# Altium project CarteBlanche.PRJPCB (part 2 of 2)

## Sheet FPGAPOWER.SchDoc: FPGA POWER CONFIG.
size A4; PageSetup: Record=PageOptions|CenterHorizontal=True|CenterVertical=True|PrintScale=0.70|XCorrection=1.00|YCorrection=1.00|PrintKind=0|BorderSize=5000000|LeftOffset=0|BottomOffset=0|Orientation=2|PaperLength=1000|PaperWidth=1000|Scale=100|PaperSource=7|PrintQuality=1200|MediaType=1|DitherType=10|PaperKind=A4 (210 x 297 mm)|PrintScaleMode=1; CheckedBy: SRKH; Author: SRKH; Engineer: SRKH; DocumentNumber: 3; Revision: CB500E; SheetNumber: 3; SheetTotal: 18; DrawnBy: SRKH; Address1: WWW.APPLELOGIC.ORG
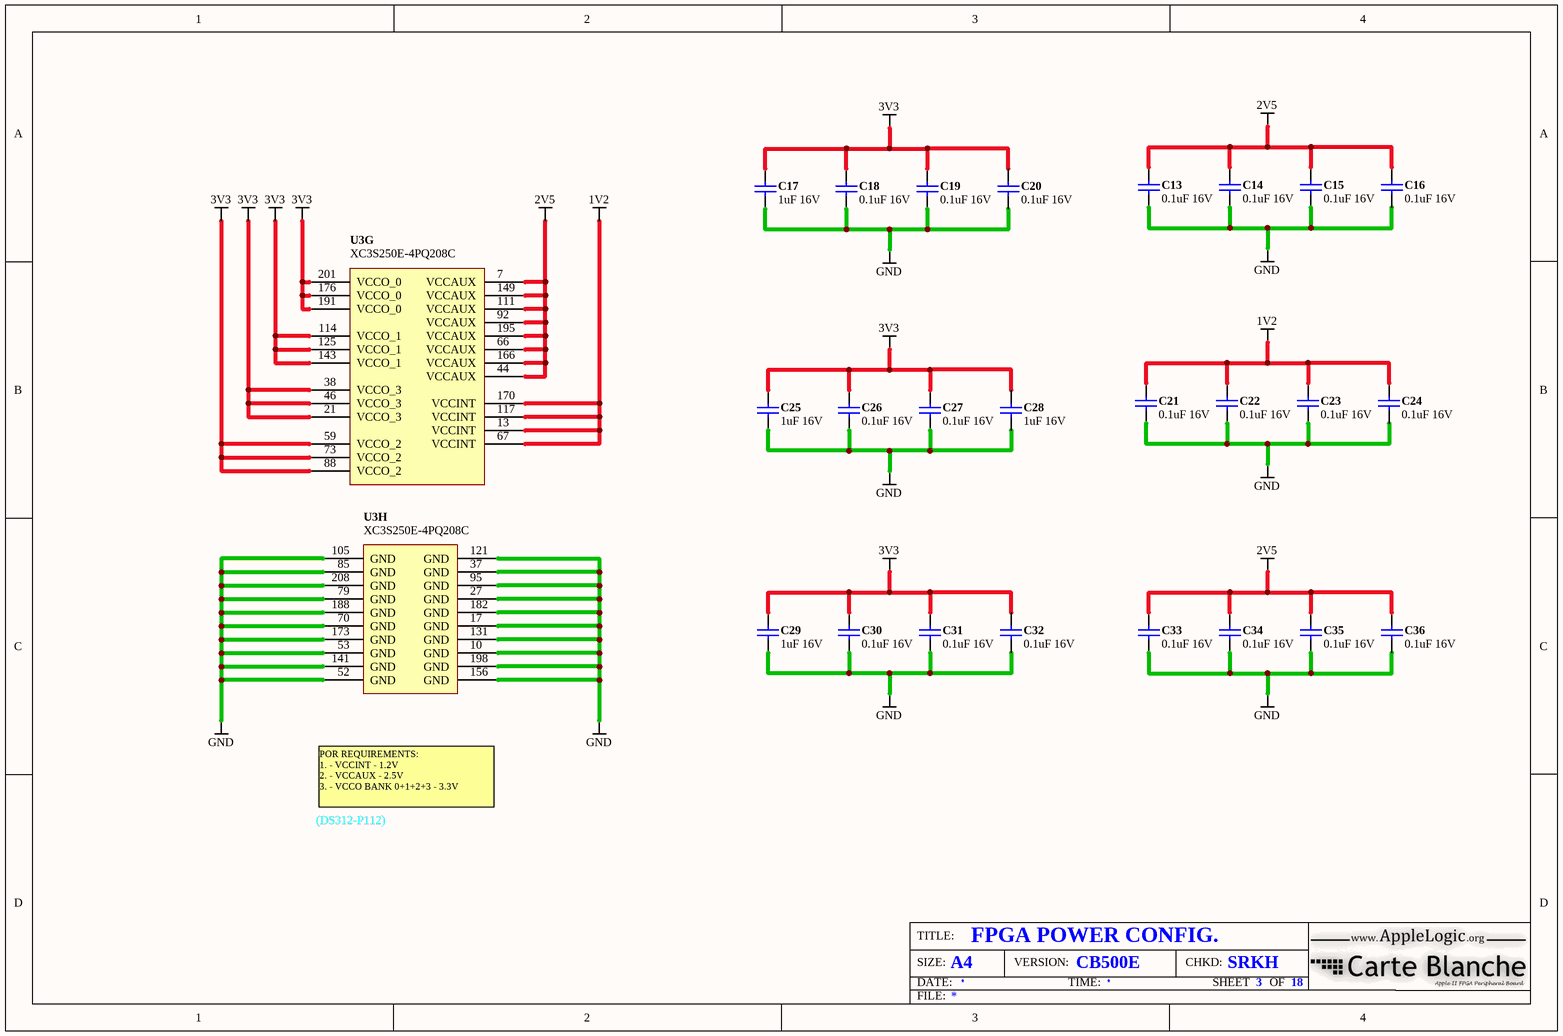
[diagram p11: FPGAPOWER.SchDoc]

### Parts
(Parts that share a designator on the sheet are numbered #1, #2 ... from top to bottom, then left to right.)
C13  0.1uF 16V  [CAPC1005-STAR]
C14  0.1uF 16V  [CAPC1005-STAR]
C15  0.1uF 16V  [CAPC1005-STAR]
C16  0.1uF 16V  [CAPC1005-STAR]
C17  1uF 16V  [CAPC1005-STAR]
C18  0.1uF 16V  [CAPC1005-STAR]
C19  0.1uF 16V  [CAPC1005-STAR]
C20  0.1uF 16V  [CAPC1005-STAR]
C21  0.1uF 16V  [CAPC1005-STAR]
C22  0.1uF 16V  [CAPC1005-STAR]
C23  0.1uF 16V  [CAPC1005-STAR]
C24  0.1uF 16V  [CAPC1005-STAR]
C25  1uF 16V  [CAPC1005-STAR]
C26  0.1uF 16V  [CAPC1005-STAR]
C27  0.1uF 16V  [CAPC1005-STAR]
C28  1uF 16V  [CAPC1005-STAR]
C29  1uF 16V  [CAPC1005-STAR]
C30  0.1uF 16V  [CAPC1005-STAR]
C31  0.1uF 16V  [CAPC1005-STAR]
C32  0.1uF 16V  [CAPC1005-STAR]
C33  0.1uF 16V  [CAPC1005-STAR]
C34  0.1uF 16V  [CAPC1005-STAR]
C35  0.1uF 16V  [CAPC1005-STAR]
C36  0.1uF 16V  [CAPC1005-STAR]
U3#1  XC3S250E-4PQ208C  [PQ208_N]  (part H of 8)
U3#2  XC3S250E-4PQ208C  [PQ208_N]  (part G of 8)

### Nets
1V2: C21.2 C22.2 C23.2 C24.1 U3#2.13(VCCINT) U3#2.67(VCCINT) U3#2.117(VCCINT) U3#2.170(VCCINT)
2V5: C13.2 C14.2 C15.2 C16.1 C33.2 C34.2 C35.2 C36.1 U3#2.7(VCCAUX) U3#2.44(VCCAUX) U3#2.66(VCCAUX) U3#2.92(VCCAUX) U3#2.111(VCCAUX) U3#2.149(VCCAUX) U3#2.166(VCCAUX) U3#2.195(VCCAUX)
3V3: C17.1 C18.1 C19.2 C20.2 C25.2 C26.2 C27.2 C28.2 C29.2 C30.2 C31.2 C32.2 U3#2.21(VCCO_3) U3#2.38(VCCO_3) U3#2.46(VCCO_3) U3#2.59(VCCO_2) U3#2.73(VCCO_2) U3#2.88(VCCO_2) U3#2.114(VCCO_1) U3#2.125(VCCO_1) U3#2.143(VCCO_1) U3#2.176(VCCO_0) U3#2.191(VCCO_0) U3#2.201(VCCO_0)
GND: C13.1 C14.1 C15.1 C16.2 C17.2 C18.2 C19.1 C20.1 C21.1 C22.1 C23.1 C24.2 C25.1 C26.1 C27.1 C28.1 C29.1 C30.1 C31.1 C32.1 C33.1 C34.1 C35.1 C36.2 U3#1.10(GND) U3#1.17(GND) U3#1.27(GND) U3#1.37(GND) U3#1.52(GND) U3#1.53(GND) U3#1.70(GND) U3#1.79(GND) U3#1.85(GND) U3#1.95(GND) U3#1.105(GND) U3#1.121(GND) U3#1.131(GND) U3#1.141(GND) U3#1.156(GND) U3#1.173(GND) U3#1.182(GND) U3#1.188(GND) U3#1.198(GND) U3#1.208(GND)

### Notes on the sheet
- (DS312-P112)
- POR REQUIREMENTS:
  1. - VCCINT - 1.2V
  2. - VCCAUX - 2.5V
  3. - VCCO BANK 0+1+2+3 - 3.3V

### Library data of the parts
C13-C36 = CAP-NP: Capacitor, Ceramic, 1uF 10% 16V 0402 (1005) X7R
U3#1 = XC3S500E-4PQ208C: IC SPARTAN-3E FPGA 500K 208-PQFP; EnablePinSwap: True
U3#2 = XC3S250E-4PQ208C: IC SPARTAN-3E FPGA 500K 208-PQFP; EnablePinSwap: True

## Sheet SRAM-128Kx8x2.SchDoc: 256K x8 SRAM MEMORY
size A4; PageSetup: Record=PageOptions|CenterHorizontal=True|CenterVertical=True|PrintScale=0.50|XCorrection=1.00|YCorrection=1.00|PrintKind=0|BorderSize=5000000|LeftOffset=0|BottomOffset=0|Orientation=2|PaperLength=1000|PaperWidth=1000|Scale=100|PaperSource=7|PrintQuality=600|MediaType=1|DitherType=10|PaperKind=12" x 18"|PrintScaleMode=1; CheckedBy: SRKH; Author: SRKH; Engineer: SRKH; DocumentNumber: 11; Revision: CB500E; SheetNumber: 11; SheetTotal: 18; DrawnBy: SRKH; Address1: WWW.APPLELOGIC.ORG
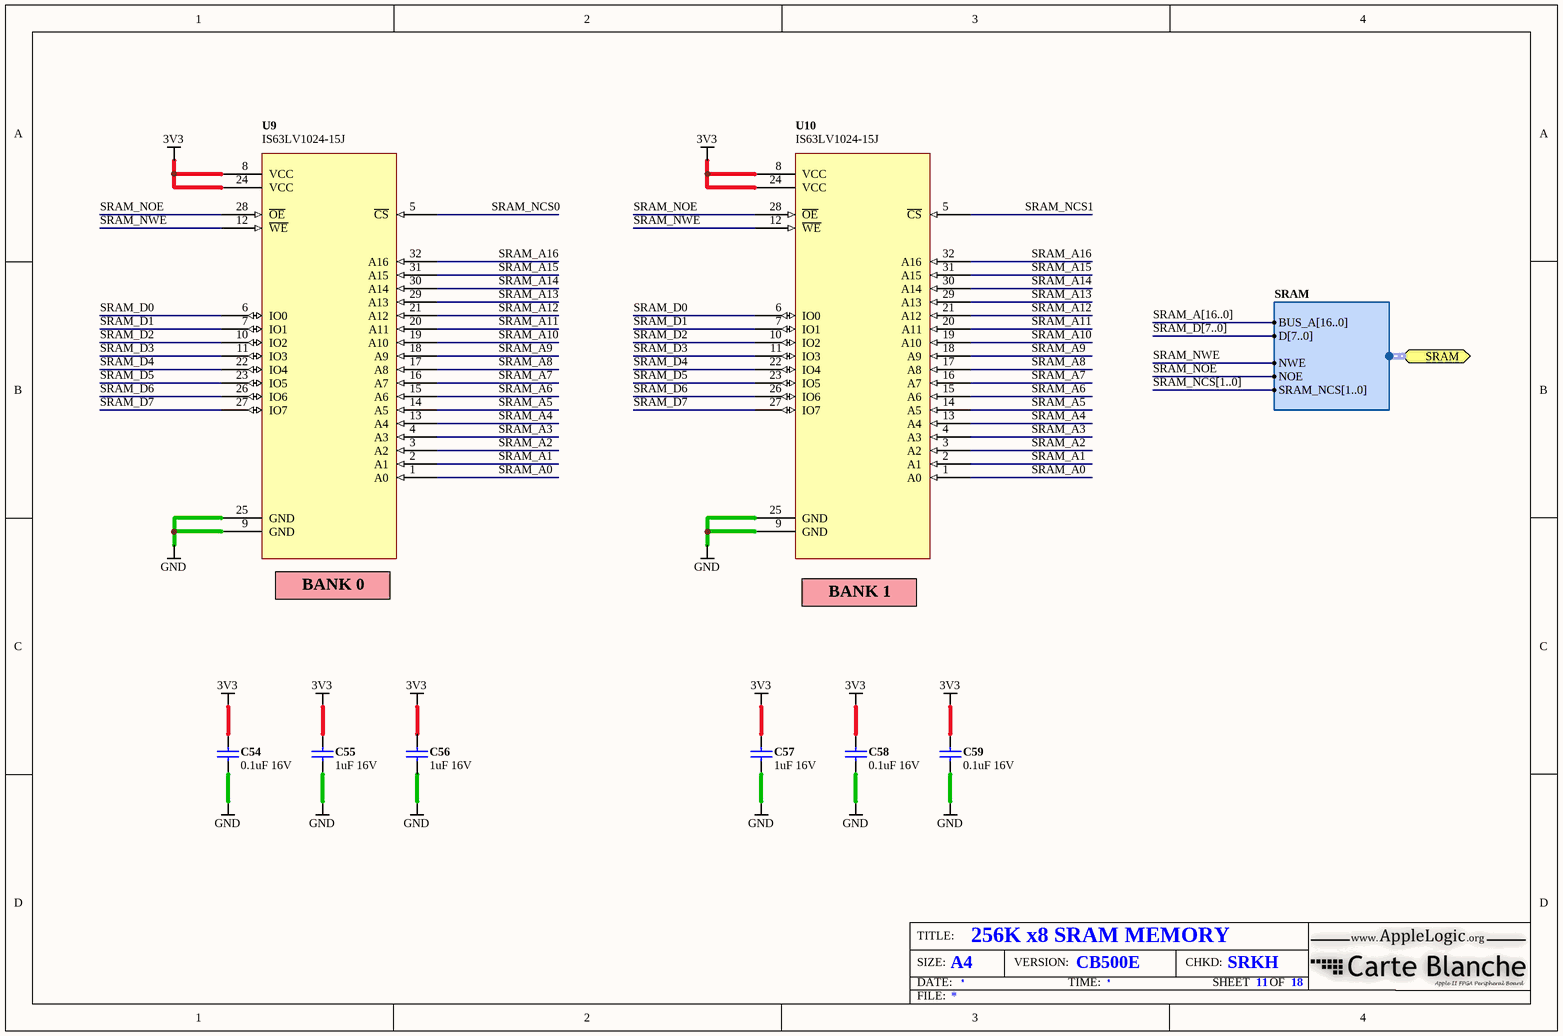
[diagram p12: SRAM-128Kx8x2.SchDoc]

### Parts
C54  0.1uF 16V  [CAPC1005-STAR]
C55  1uF 16V  [CAPC1005-STAR]
C56  1uF 16V  [CAPC1005-STAR]
C57  1uF 16V  [CAPC1005-STAR]
C58  0.1uF 16V  [CAPC1005-STAR]
C59  0.1uF 16V  [CAPC1005-STAR]
U9  IS63LV1024-15J  [SO-J32]
U10  IS63LV1024-15J  [SO-J32]

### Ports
SRAM (harness SRAM)

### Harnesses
SRAM: BUS_A[16..0], D[7..0], NWE, SRAM_NCS[1..0], NOE

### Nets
3V3: C54.1 C55.1 C56.1 C57.1 C58.1 C59.1 U9.8(VCC) U9.24(VCC) U10.8(VCC) U10.24(VCC)
GND: C54.2 C55.2 C56.2 C57.2 C58.2 C59.2 U9.9(GND) U9.25(GND) U10.9(GND) U10.25(GND)
SRAM_A0: U9.1(A0) U10.1(A0)
SRAM_A1: U9.2(A1) U10.2(A1)
SRAM_A2: U9.3(A2) U10.3(A2)
SRAM_A3: U9.4(A3) U10.4(A3)
SRAM_A4: U9.13(A4) U10.13(A4)
SRAM_A5: U9.14(A5) U10.14(A5)
SRAM_A6: U9.15(A6) U10.15(A6)
SRAM_A7: U9.16(A7) U10.16(A7)
SRAM_A8: U9.17(A8) U10.17(A8)
SRAM_A9: U9.18(A9) U10.18(A9)
SRAM_A10: U9.19(A10) U10.19(A10)
SRAM_A11: U9.20(A11) U10.20(A11)
SRAM_A12: U9.21(A12) U10.21(A12)
SRAM_A13: U9.29(A13) U10.29(A13)
SRAM_A14: U9.30(A14) U10.30(A14)
SRAM_A15: U9.31(A15) U10.31(A15)
SRAM_A16: U9.32(A16) U10.32(A16)
SRAM_D0: U9.6(IO0) U10.6(IO0)
SRAM_D1: U9.7(IO1) U10.7(IO1)
SRAM_D2: U9.10(IO2) U10.10(IO2)
SRAM_D3: U9.11(IO3) U10.11(IO3)
SRAM_D4: U9.22(IO4) U10.22(IO4)
SRAM_D5: U9.23(IO5) U10.23(IO5)
SRAM_D6: U9.26(IO6) U10.26(IO6)
SRAM_D7: U9.27(IO7) U10.27(IO7)
SRAM_NCS0: U9.5(~{CS})
SRAM_NCS1: U10.5(~{CS})
SRAM_NOE: U9.28(~{OE}) U10.28(~{OE}) ; port SRAM.NOE  [project net RAM.NOE]
SRAM_NWE: U9.12(~{WE}) U10.12(~{WE}) ; port SRAM.NWE  [project net RAM.NWE]

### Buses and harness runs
bus SRAM_A[16..0]
bus SRAM_D[7..0]
bus SRAM_NCS[1..0]

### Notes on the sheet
- (near U9) BANK 0
- (near U10) BANK 1

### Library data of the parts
C54-C59 = CAP-NP: as C13-C36 on sheet FPGAPOWER
U9 U10 = IDT71V124SA15Y: IC SRAM 128Kx8 15nS ASYNC 32-SOJ

## Sheet M25Pxx SPI_BOOT.SchDoc: SPI SYSTEM BOOT FLASH
size A4; PageSetup: Record=PageOptions|CenterHorizontal=True|CenterVertical=True|PrintScale=1.00|XCorrection=1.00|YCorrection=1.00|PrintKind=0|BorderSize=5000000|LeftOffset=0|BottomOffset=0|Orientation=2|PaperLength=1000|PaperWidth=1000|Scale=100|PaperSource=7|PrintQuality=600|MediaType=1|DitherType=10|PaperKind=12" x 18"|PrintScaleMode=1; CheckedBy: SRKH; Author: SRKH; Engineer: SRKH; DocumentNumber: 12; Revision: CB500E; SheetNumber: 12; SheetTotal: 18; DrawnBy: SRKH; Address1: WWW.APPLELOGIC.ORG
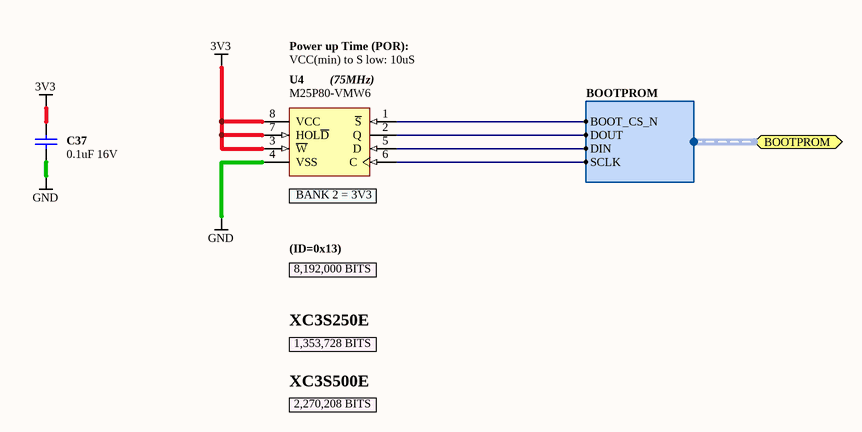
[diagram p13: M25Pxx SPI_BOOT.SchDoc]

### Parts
C37  0.1uF 16V  [CAPC1005-STAR]
U4  M25P80-VMW6  [SOIC8-200-BODY]

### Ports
BOOTPROM (harness BOOTPROM)

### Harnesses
BOOTPROM: DIN, DOUT, SCLK, BOOT_CS_N

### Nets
3V3: C37.1 U4.3(~{W}) U4.7(HOL~{D}) U4.8(VCC)
GND: C37.2 U4.4(VSS)
ROM.BOOT_CS_N: U4.1(~{S}) ; port BOOTPROM.BOOT_CS_N
ROM.DIN: U4.5(D) ; port BOOTPROM.DIN
ROM.DOUT: U4.2(Q) ; port BOOTPROM.DOUT
ROM.SCLK: U4.6(C) ; port BOOTPROM.SCLK

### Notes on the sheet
- Power up Time (POR):
- VCC(min) to S low: 10uS
- (near U4) (75MHz)
- (near U4) BANK 2 = 3V3
- (ID=0x13)
- 8,192,000 BITS
- XC3S250E
- 1,353,728 BITS
- XC3S500E
- 2,270,208 BITS

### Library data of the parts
C37 = CAP-NP: as C13-C36 on sheet FPGAPOWER
U4 = M25P80: IC SERIAL FLASH 8MBIT 3V 8-SOIC WIDE

## Sheet SVGA.SchDoc: SVGA 2BPP VIDEO PORT
size A4; CheckedBy: SRKH; Author: SRKH; DrawnBy: SRKH; Engineer: SRKH; Address1: WWW.APPLELOGIC.ORG; DocumentNumber: 13; Revision: CB500E; SheetNumber: 13; SheetTotal: 18
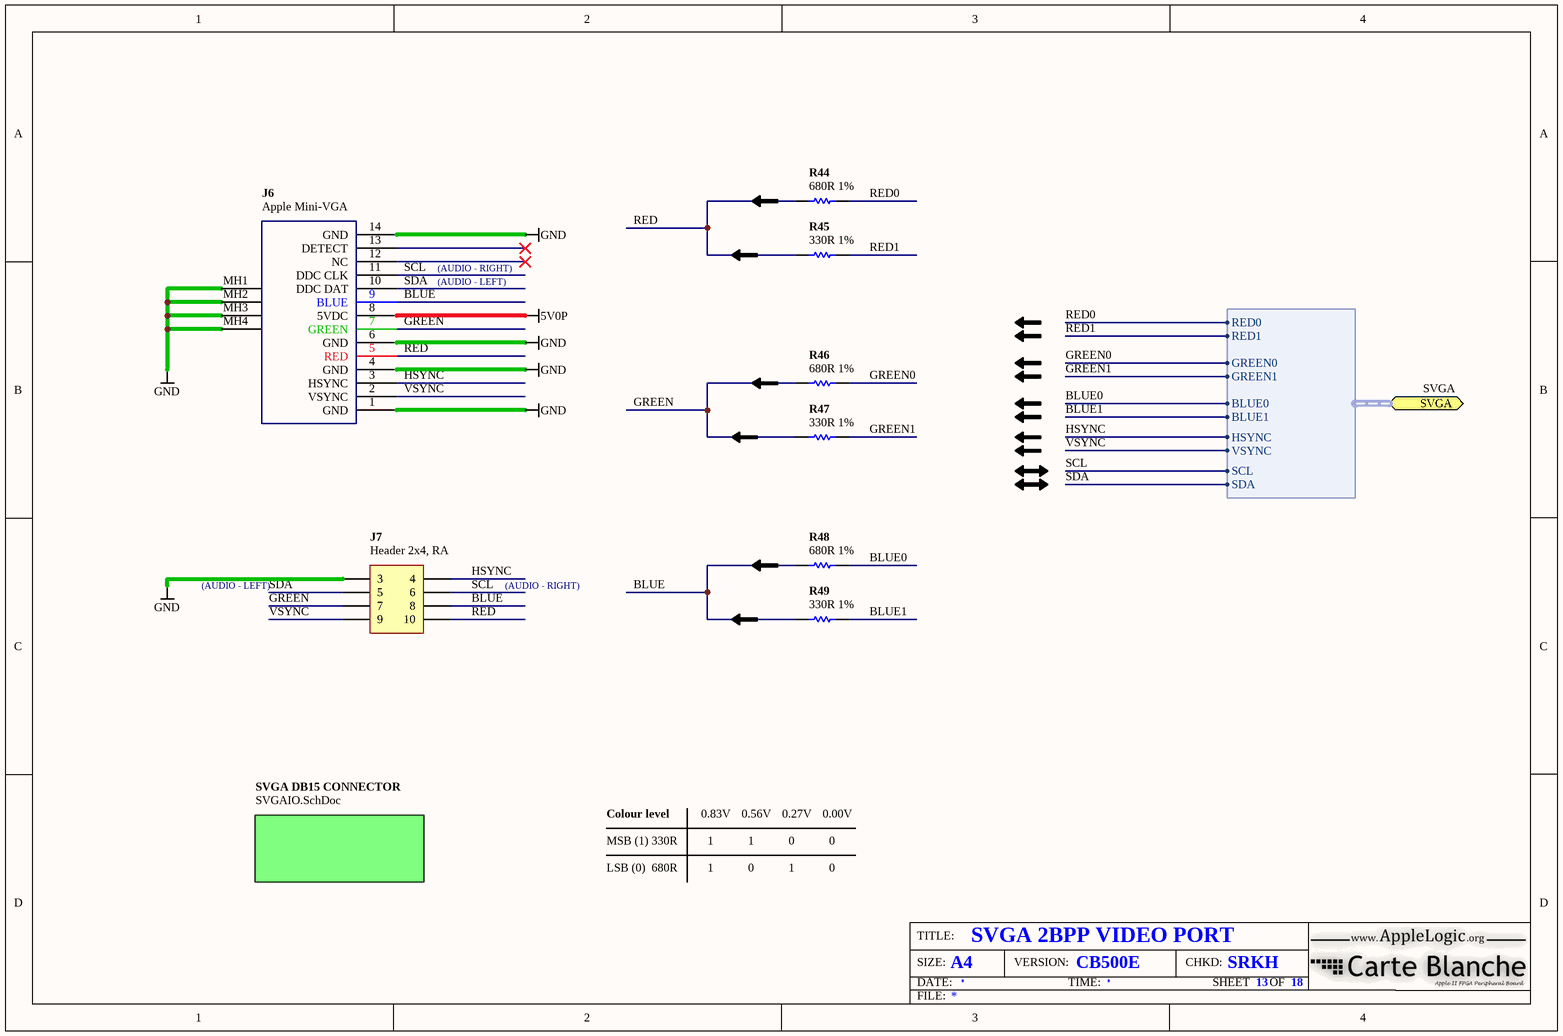
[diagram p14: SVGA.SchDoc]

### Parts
J6  Apple Mini-VGA  [CON_MINI_VGA]  (no BOM)
J7  Header 2x4, RA  [HDR2X4H]
R44  680R 1%  [RESC1005-STAR]
R45  330R 1%  [RESC1005-STAR]
R46  680R 1%  [RESC1005-STAR]
R47  330R 1%  [RESC1005-STAR]
R48  680R 1%  [RESC1005-STAR]
R49  330R 1%  [RESC1005-STAR]

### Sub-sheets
SVGA DB15 CONNECTOR = SVGAIO.SchDoc: no entries

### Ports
SVGA (harness SVGA)

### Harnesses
SVGA: BLUE0, SDA, RED0, RED1, HSYNC, VSYNC, SCL, GREEN0, GREEN1, BLUE1

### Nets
5V0P: J6.8(5VDC)
GND: J6.1(GND) J6.4(GND) J6.6(GND) J6.14(GND) J6.MH1 J6.MH2 J6.MH3 J6.MH4 J7.3
BLUE: J6.9(BLUE) J7.8 R48.1 R49.1
BLUE0: R48.2 ; port SVGA.BLUE0  [project net VGA.BLUE0]
BLUE1: R49.2 ; port SVGA.BLUE1  [project net VGA.BLUE1]
GREEN: J6.7(GREEN) J7.7 R46.1 R47.1
GREEN0: R46.2 ; port SVGA.GREEN0  [project net VGA.GREEN0]
GREEN1: R47.2 ; port SVGA.GREEN1  [project net VGA.GREEN1]
HSYNC: J6.3(HSYNC) J7.4 ; port SVGA.HSYNC  [project net VGA.HSYNC]
RED: J6.5(RED) J7.10 R44.1 R45.1
RED0: R44.2 ; port SVGA.RED0  [project net VGA.RED0]
RED1: R45.2 ; port SVGA.RED1  [project net VGA.RED1]
SCL: J6.11(DDC_CLK) J7.6 ; port SVGA.SCL  [project net VGA.SCL]
SDA: J6.10(DDC_DAT) J7.5 ; port SVGA.SDA  [project net VGA.SDA]
VSYNC: J6.2(VSYNC) J7.9 ; port SVGA.VSYNC  [project net VGA.VSYNC]

Not connected (* = marked no-connect by the designer): J6 12(NC)* 13(DETECT)*

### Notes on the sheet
- (AUDIO - LEFT)
- (AUDIO - RIGHT)
- Colour level
- MSB (1) 330R
- 0.83V
- 1
- 0.56V
- 0.27V
- 0
- 0.00V
- LSB (0)  680R

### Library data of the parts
J6 = CON-MINI_VGA: Socket, VGA/RGB Connector, 1.00mm Pitch, Through-hole, Suyin
J7 = Header 4X2H: Header, Right Angle, 8-Pin, Dual row
R44-R49 = RES: Resistor, 4K7 1% 0402 (1005)

## Sheet SVGAIO.SchDoc: AII SVGA MOUNTING BOARD
size A4; CheckedBy: SRKH; Author: SRKH; DrawnBy: SRKH; Engineer: SRKH; Address1: WWW.APPLELOGIC.ORG; DocumentNumber: 18; Revision: CB500E; SheetNumber: 18; SheetTotal: 18
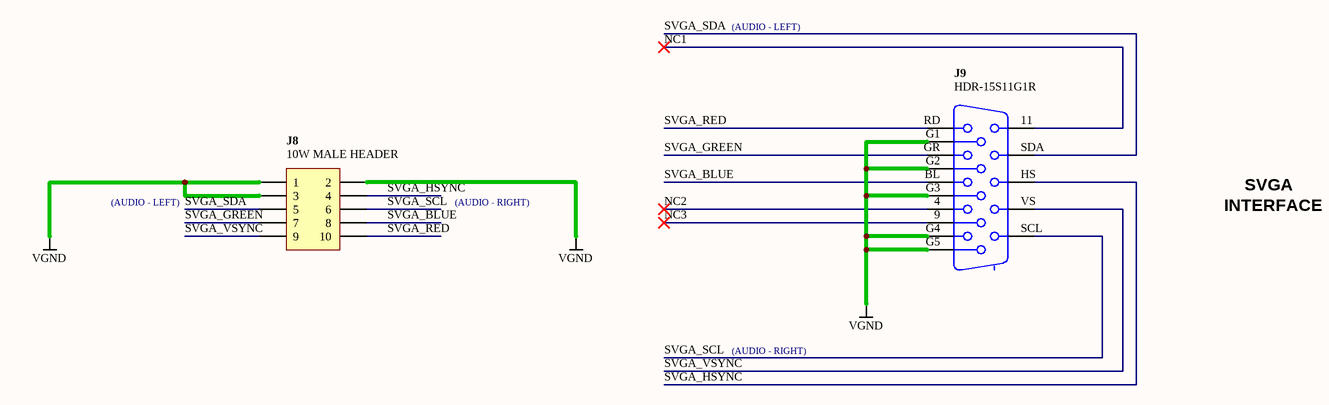
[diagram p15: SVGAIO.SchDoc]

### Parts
J8  10W MALE HEADER  [918510X323]
J9  HDR-15S11G1R  [DB15-VGA-Female]

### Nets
VGND: J8.1 J8.2 J8.3 J9.G1 J9.G2 J9.G3 J9.G4 J9.G5
NC1: J9.11
NC2: J9.4
NC3: J9.9
SVGA_BLUE: J8.8 J9.BL
SVGA_GREEN: J8.7 J9.GR
SVGA_HSYNC: J8.4 J9.HS
SVGA_RED: J8.10 J9.RD
SVGA_SCL: J8.6 J9.SCL
SVGA_SDA: J8.5 J9.SDA
SVGA_VSYNC: J8.9 J9.VS

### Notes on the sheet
- (AUDIO - LEFT)
- (AUDIO - RIGHT)
- INTERFACE
- SVGA

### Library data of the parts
J8 = CON-IDC-2x5-M-RA: Header IDC, 2x5 Pin Right-Angle 2.54mm Pitch (Boxed-Male)
J9 = CON-DB-15-F-RA: Socket, High-Density DB15 (HD15) Female Through-hole

## Sheet SDIO.SchDoc: SDIO INTERFACE
size A4; PageSetup: Record=PageOptions|CenterHorizontal=True|CenterVertical=True|PrintScale=0.50|XCorrection=1.00|YCorrection=1.00|PrintKind=0|BorderSize=5000000|LeftOffset=0|BottomOffset=0|Orientation=2|PaperLength=1000|PaperWidth=1000|Scale=100|PaperSource=7|PrintQuality=600|MediaType=1|DitherType=10|PaperKind=12" x 18"|PrintScaleMode=1; CheckedBy: SRKH; Author: SRKH; Engineer: SRKH; DocumentNumber: 15; Revision: CB500E; SheetNumber: 15; SheetTotal: 18; DrawnBy: SRKH; Address1: WWW.APPLELOGIC.ORG
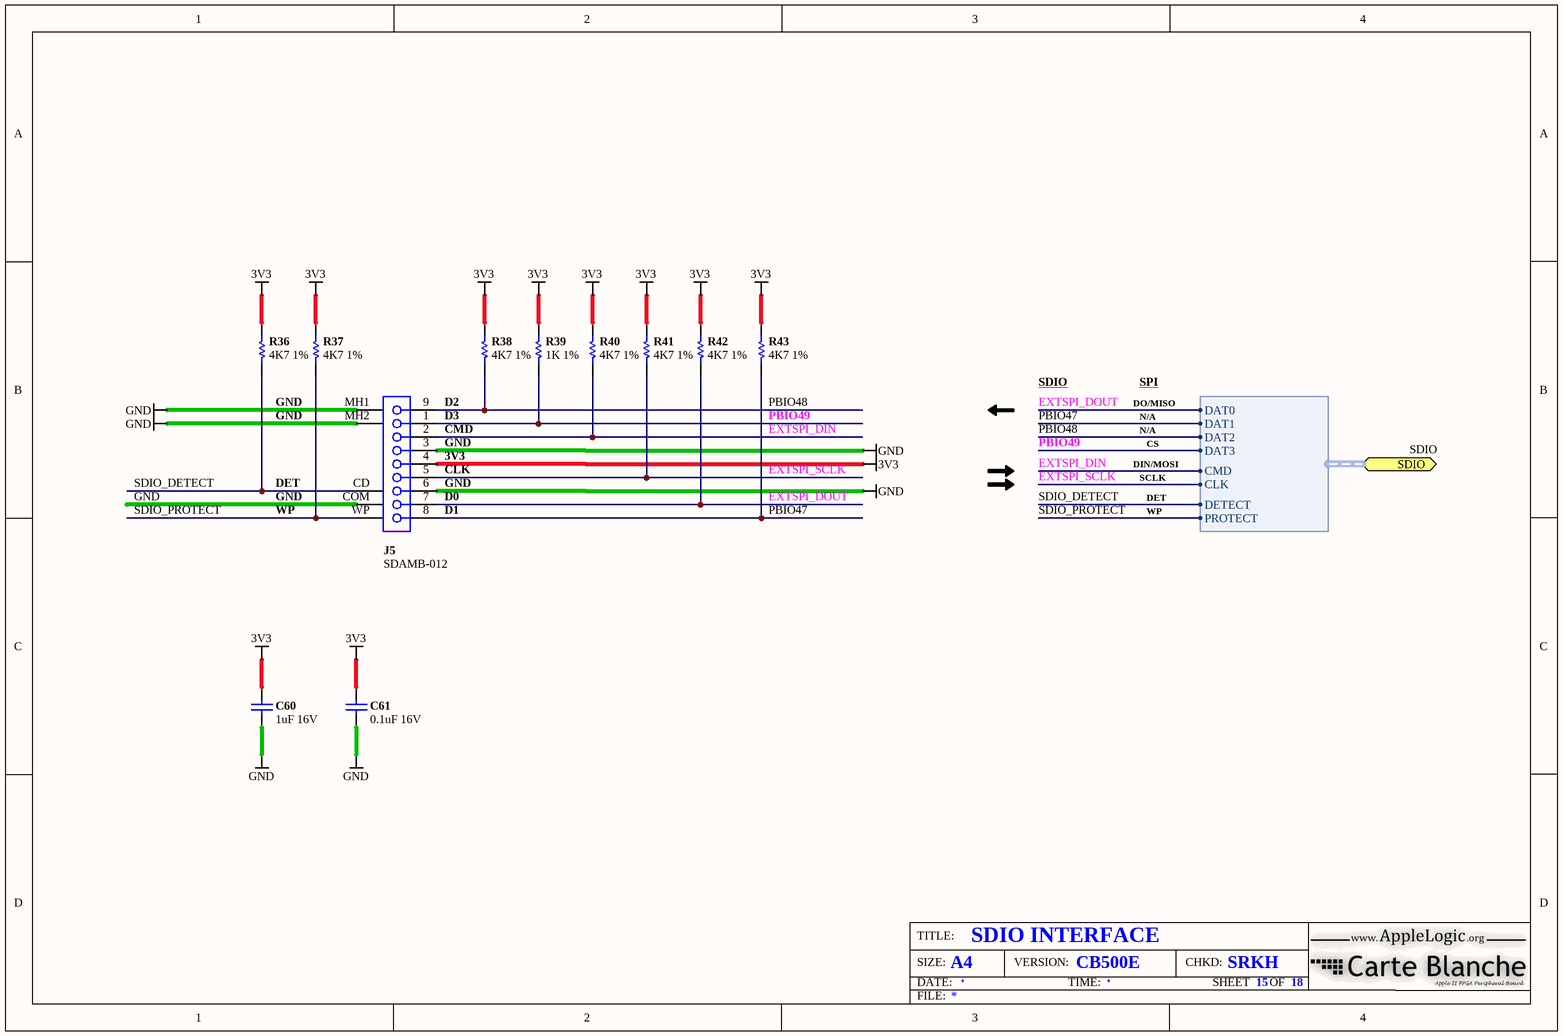
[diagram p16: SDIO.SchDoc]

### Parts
C60  1uF 16V  [CAPC1005-STAR]
C61  0.1uF 16V  [CAPC1005-STAR]
J5  SDAMB-012  [SDAMB-012]
R36  4K7 1%  [RESC1005-STAR]
R37  4K7 1%  [RESC1005-STAR]
R38  4K7 1%  [RESC1005-STAR]
R39  1K 1%  [RESC1005-STAR]
R40  4K7 1%  [RESC1005-STAR]
R41  4K7 1%  [RESC1005-STAR]
R42  4K7 1%  [RESC1005-STAR]
R43  4K7 1%  [RESC1005-STAR]

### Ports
SDIO (harness SDIO)

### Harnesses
SDIO: DAT0, CMD, CLK, PROTECT, DETECT, DAT1, DAT2, DAT3

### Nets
3V3: C60.2 C61.2 J5.4 R36.2 R37.2 R38.2 R39.2 R40.2 R41.2 R42.2 R43.2
GND: C60.1 C61.1 J5.3 J5.6 J5.COM J5.MH1 J5.MH2
EXTSPI_DIN: J5.2 R40.1 ; port SDIO.CMD  [project net ROM.DIN]
EXTSPI_DOUT: J5.7 R42.1 ; port SDIO.DAT0  [project net ROM.DOUT]
EXTSPI_SCLK: J5.5 R41.1 ; port SDIO.CLK  [project net ROM.SCLK]
PBIO47: J5.8 R43.1 ; port SDIO.DAT1  [project net SD.DAT1]
PBIO48: J5.9 R38.1 ; port SDIO.DAT2  [project net SD.DAT2]
PBIO49: J5.1 R39.1 ; port SDIO.DAT3  [project net SD.DAT3]
SDIO_DETECT: J5.CD R36.1 ; port SDIO.DETECT  [project net SD.DETECT]
SDIO_PROTECT: J5.WP R37.1 ; port SDIO.PROTECT  [project net SD.PROTECT]

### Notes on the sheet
- SDIO
- SPI
- GND
- D2
- (near J5) D3
- (near J5) CMD
- (near J5) GND
- DO/MISO
- N/A
- CS
- DET
- WP
- (near J5) CLK
- (near J5) D0
- (near J5) D1
- (near J5) 3V3
- DIN/MOSI
- SCLK

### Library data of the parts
C60 C61 = CAP-NP: as C13-C36 on sheet FPGAPOWER
J5 = SDAMB-012: KINGFONT SDCARD Connector SDAMB-012
R36-R43 = RES: Resistor, 4K7 1% 0402 (1005)

## Sheet IDE.SchDoc: IDE INTERFACE
size A4; PageSetup: Record=PageOptions|CenterHorizontal=True|CenterVertical=True|PrintScale=0.50|XCorrection=1.00|YCorrection=1.00|PrintKind=0|BorderSize=5000000|LeftOffset=0|BottomOffset=0|Orientation=2|PaperLength=1000|PaperWidth=1000|Scale=100|PaperSource=7|PrintQuality=600|MediaType=1|DitherType=10|PaperKind=12" x 18"|PrintScaleMode=1; CheckedBy: SRKH; Author: SRKH; Engineer: SRKH; DocumentNumber: 14; Revision: CB500E; SheetNumber: 14; SheetTotal: 18; DrawnBy: SRKH; Address1: WWW.APPLELOGIC.ORG
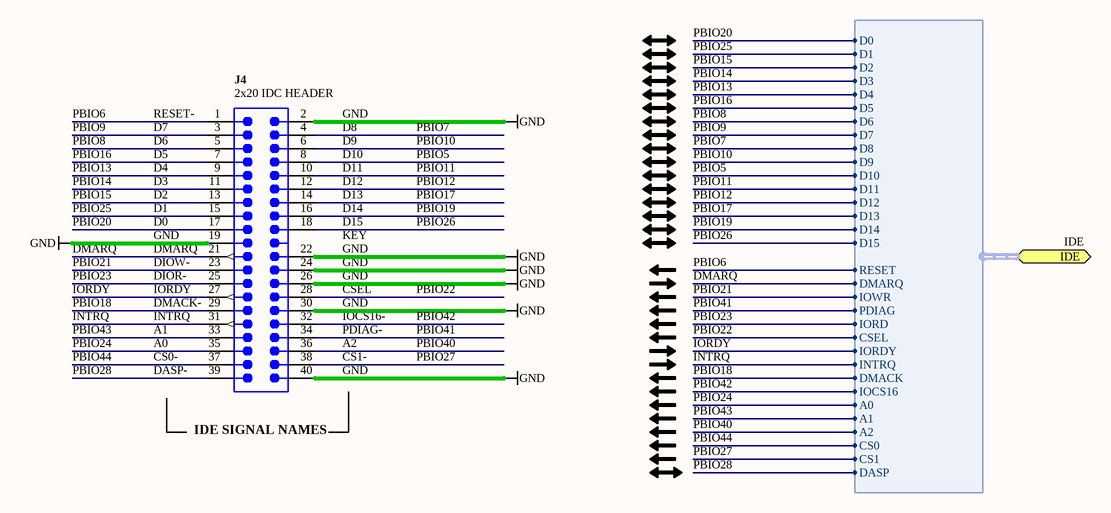
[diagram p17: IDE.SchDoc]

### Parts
J4  2x20 IDC HEADER  [918540x324]

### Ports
IDE (harness IDE)

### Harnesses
IDE: CS1, A2, D3, INTRQ, IORD, IOWR, DASP, RESET, CSEL, IOCS16, DMARQ, DMACK, PDIAG, IORDY, CS0, A1, A0, D4, D5, D6, D7, D8, D9, D10, D11, D12, D13, D14, D15, D2, D1, D0

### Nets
GND: J4.2 J4.19 J4.22 J4.24 J4.26 J4.30 J4.40
DMARQ: J4.21 ; port IDE.DMARQ  [project net IDE.DMARQ]
INTRQ: J4.31 ; port IDE.INTRQ  [project net IDE.INTRQ]
IORDY: J4.27 ; port IDE.IORDY  [project net IDE.IORDY]
PBIO5: J4.8 ; port IDE.D10  [project net IDE.D10]
PBIO6: J4.1 ; port IDE.RESET  [project net IDE.RESET]
PBIO7: J4.4 ; port IDE.D8  [project net IDE.D8]
PBIO8: J4.5 ; port IDE.D6  [project net IDE.D6]
PBIO9: J4.3 ; port IDE.D7  [project net IDE.D7]
PBIO10: J4.6 ; port IDE.D9  [project net IDE.D9]
PBIO11: J4.10 ; port IDE.D11  [project net IDE.D11]
PBIO12: J4.12 ; port IDE.D12  [project net IDE.D12]
PBIO13: J4.9 ; port IDE.D4  [project net IDE.D4]
PBIO14: J4.11 ; port IDE.D3  [project net IDE.D3]
PBIO15: J4.13 ; port IDE.D2  [project net IDE.D2]
PBIO16: J4.7 ; port IDE.D5  [project net IDE.D5]
PBIO17: J4.14 ; port IDE.D13  [project net IDE.D13]
PBIO18: J4.29 ; port IDE.DMACK  [project net IDE.DMACK]
PBIO19: J4.16 ; port IDE.D14  [project net IDE.D14]
PBIO20: J4.17 ; port IDE.D0  [project net IDE.D0]
PBIO21: J4.23 ; port IDE.IOWR  [project net IDE.IOWR]
PBIO22: J4.28 ; port IDE.CSEL  [project net IDE.CSEL]
PBIO23: J4.25 ; port IDE.IORD  [project net IDE.IORD]
PBIO24: J4.35 ; port IDE.A0  [project net IDE.A0]
PBIO25: J4.15 ; port IDE.D1  [project net IDE.D1]
PBIO26: J4.18 ; port IDE.D15  [project net IDE.D15]
PBIO27: J4.38 ; port IDE.CS1  [project net IDE.CS1]
PBIO28: J4.39 ; port IDE.DASP  [project net IDE.DASP]
PBIO40: J4.36 ; port IDE.A2  [project net IDE.A2]
PBIO41: J4.34 ; port IDE.PDIAG  [project net IDE.PDIAG]
PBIO42: J4.32 ; port IDE.IOCS16  [project net IDE.IOCS16]
PBIO43: J4.33 ; port IDE.A1  [project net IDE.A1]
PBIO44: J4.37 ; port IDE.CS0  [project net IDE.CS0]

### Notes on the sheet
- (near J4) RESET-
- GND
- D7
- D4
- D5
- D6
- D8
- D9
- D10
- D11
- D0
- D1
- D2
- D3
- (near J4) DMARQ
- D12
- D13
- D14
- D15
- KEY
- (near J4) DMACK-
- (near J4) IORDY
- (near J4) DIOR-
- (near J4) DIOW-
- CSEL
- (near J4) DASP-
- CS0-
- A0
- A1
- (near J4) INTRQ
- IOCS16-
- PDIAG-
- A2
- CS1-
- (near J4) IDE SIGNAL NAMES

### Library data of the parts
J4 = CON-IDC-2x20-M-STR: Header, Boxed 2x20 Pin Vertical 2.54mm Pitch

## Sheet SYSCLK.SchDoc: 14.31818MHZ SYS CLOCK
size A4; PageSetup: Record=PageOptions|CenterHorizontal=True|CenterVertical=True|PrintScale=0.50|XCorrection=1.00|YCorrection=1.00|PrintKind=0|BorderSize=5000000|LeftOffset=0|BottomOffset=0|Orientation=2|PaperLength=1000|PaperWidth=1000|Scale=100|PaperSource=7|PrintQuality=600|MediaType=1|DitherType=10|PaperKind=12" x 18"|PrintScaleMode=1; CheckedBy: SRKH; Author: SRKH; Engineer: SRKH; DocumentNumber: 16; Revision: CB500E; SheetNumber: 16; SheetTotal: 18; DrawnBy: SRKH; Address1: WWW.APPLELOGIC.ORG
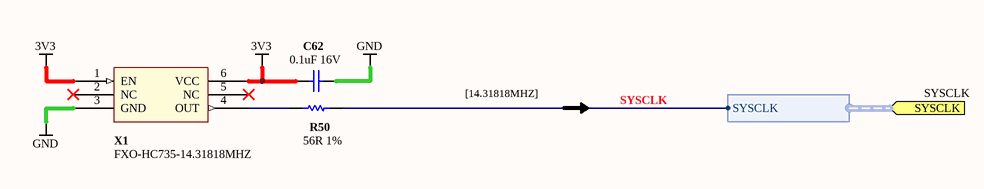
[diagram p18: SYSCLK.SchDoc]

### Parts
C62  0.1uF 16V  [CAPC1005-STAR]
R50  56R 1%  [RESC1005-STAR]
X1  FXO-HC735-14.31818MHZ  [OSCILLATOR-5x7-FOX-XPRESS0]

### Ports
SYSCLK (harness SYSCLK)

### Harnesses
SYSCLK: SYSCLK

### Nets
3V3: C62.1 X1.1(EN) X1.6(VCC)
GND: C62.2 X1.3(GND)
SYSCLK: R50.2 ; port SYSCLK.SYSCLK  [project net SYSCLK.SYSCLK]
NetR50_1: R50.1 X1.4(OUT)

Not connected (* = marked no-connect by the designer): X1 2(NC)* 5(NC)*

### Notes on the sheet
- [14.31818MHZ]

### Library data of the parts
C62 = CAP-NP: as C13-C36 on sheet FPGAPOWER
R50 = RES: Resistor, 4K7 1% 0402 (1005)
X1 = OSCILLATOR-5x7-FOX-XPRESS0: OSCILLATOR 14.31818 MHZ 3.3V SMD

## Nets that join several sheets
1V2: PSU_1084_1V2 (NT3.2), FPGAPOWER (8 pins)
1V2P: PERIPHERAL (HDR1.73 HDR1.75), PSU_1084_1V2 (5 pins)
1V8P: PERIPHERAL (HDR1.77 HDR1.79), PSU_1084_1V8 (5 pins)
2V5: XC3S500E-4PQ208 (R29.2 R35.2), PSU_1084_2V5 (NT5.2), FPGAPOWER (16 pins)
2V5P: PERIPHERAL (HDR1.81 HDR1.83), PSU_1084_2V5 (5 pins)
3V3: APPLEIISLOT (C1.1), CON_10WBOXHDREDGEM (8 pins), XC3S500E-4PQ208 (5 pins), PSU_1084_3V3 (NT6.2), FPGAPOWER (24 pins), SRAM-128Kx8x2 (10 pins), M25Pxx SPI_BOOT (C37.1 U4.3 U4.7 U4.8), SDIO (11 pins), SYSCLK (C62.1 X1.1 X1.6)
3V3P: PERIPHERAL (HDR1.85 HDR1.87), PSU_1084_3V3 (5 pins)
5V0P: APPLEIISLOT (C2.1 J1.25), LEVELTRANSLATOR (C10.1 D1.1 D1.2), PERIPHERAL (6 pins), PSU_1084_1V2 (C38.1 C39.1 U5.3), PSU_1084_1V8 (C42.1 C43.1 U6#1.3), PSU_1084_2V5 (C46.1 C47.1 U6#2.3), PSU_1084_3V3 (C50.1 C51.1 U7.3), SVGA (J6.8)
+12V: APPLEIISLOT (J1.50), PERIPHERAL (R12.2)
_5V0: APPLEIISLOT (J1.34), PERIPHERAL (R15.2)
_12V: APPLEIISLOT (J1.33), PERIPHERAL (R13.2)
GND: APPLEIISLOT (C1.2 C2.2 J1.26), CON_10WBOXHDREDGEM (J2.9), XC3S500E-4PQ208 (6 pins), LEVELTRANSLATOR (39 pins), PERIPHERAL (19 pins), PSU_1084_1V2 (5 pins), PSU_1084_1V8 (5 pins), PSU_1084_2V5 (5 pins), PSU_1084_3V3 (5 pins), FPGAPOWER (44 pins), SRAM-128Kx8x2 (10 pins), M25Pxx SPI_BOOT (C37.2 U4.4), SVGA (9 pins), SDIO (7 pins), IDE (7 pins), SYSCLK (C62.2 X1.3)
AIIB.-BUS-DEV_SEL: XC3S500E-4PQ208 (U3#1.14), LEVELTRANSLATOR (U1.44)
AIIB.-BUS-IO_SEL: XC3S500E-4PQ208 (U3#1.204), LEVELTRANSLATOR (U1.74)
AIIB.BUS-3M58: XC3S500E-4PQ208 (U3#1.51), LEVELTRANSLATOR (U2.64)
AIIB.BUS-7M: XC3S500E-4PQ208 (U3#1.80), LEVELTRANSLATOR (U2.66)
AIIB.BUS-A0: XC3S500E-4PQ208 (U3#1.4), LEVELTRANSLATOR (U1.72)
AIIB.BUS-A1: XC3S500E-4PQ208 (U3#1.8), LEVELTRANSLATOR (U1.66)
AIIB.BUS-A2: XC3S500E-4PQ208 (U3#1.11), LEVELTRANSLATOR (U1.64)
AIIB.BUS-A3: XC3S500E-4PQ208 (U3#1.9), LEVELTRANSLATOR (U1.62)
AIIB.BUS-A4: XC3S500E-4PQ208 (U3#1.12), LEVELTRANSLATOR (U1.56)
AIIB.BUS-A5: XC3S500E-4PQ208 (U3#1.31), LEVELTRANSLATOR (U1.54)
AIIB.BUS-A6: XC3S500E-4PQ208 (U3#1.33), LEVELTRANSLATOR (U1.52)
AIIB.BUS-A7: XC3S500E-4PQ208 (U3#1.30), LEVELTRANSLATOR (U1.45)
AIIB.BUS-A8: XC3S500E-4PQ208 (U3#1.23), LEVELTRANSLATOR (U1.43)
AIIB.BUS-A9: XC3S500E-4PQ208 (U3#1.22), LEVELTRANSLATOR (U1.41)
AIIB.BUS-A10: XC3S500E-4PQ208 (U3#1.36), LEVELTRANSLATOR (U2.75)
AIIB.BUS-A11: XC3S500E-4PQ208 (U3#1.39), LEVELTRANSLATOR (U2.73)
AIIB.BUS-A12: XC3S500E-4PQ208 (U3#1.40), LEVELTRANSLATOR (U2.71)
AIIB.BUS-A13: XC3S500E-4PQ208 (U3#1.47), LEVELTRANSLATOR (U2.65)
AIIB.BUS-A14: XC3S500E-4PQ208 (U3#1.48), LEVELTRANSLATOR (U2.63)
AIIB.BUS-A15: XC3S500E-4PQ208 (U3#1.49), LEVELTRANSLATOR (U2.62)
AIIB.BUS-D0: XC3S500E-4PQ208 (U3#1.3), LEVELTRANSLATOR (U1.73)
AIIB.BUS-D1: XC3S500E-4PQ208 (U3#1.5), LEVELTRANSLATOR (U1.71)
AIIB.BUS-D2: XC3S500E-4PQ208 (U3#1.16), LEVELTRANSLATOR (U1.65)
AIIB.BUS-D3: XC3S500E-4PQ208 (U3#1.19), LEVELTRANSLATOR (U1.63)
AIIB.BUS-D4: XC3S500E-4PQ208 (U3#1.18), LEVELTRANSLATOR (U1.61)
AIIB.BUS-D5: XC3S500E-4PQ208 (U3#1.29), LEVELTRANSLATOR (U1.55)
AIIB.BUS-D6: XC3S500E-4PQ208 (U3#1.24), LEVELTRANSLATOR (U1.53)
AIIB.BUS-D7: XC3S500E-4PQ208 (U3#1.35), LEVELTRANSLATOR (U1.51)
AIIB.BUS-DMA: XC3S500E-4PQ208 (U3#1.41), LEVELTRANSLATOR (U2.46)
AIIB.BUS-DMAIN: XC3S500E-4PQ208 (U3#1.72), LEVELTRANSLATOR (U2.42)
AIIB.BUS-DMAOUT: XC3S500E-4PQ208 (U3#1.69), LEVELTRANSLATOR (U2.41)
AIIB.BUS-INH: XC3S500E-4PQ208 (U3#1.45), LEVELTRANSLATOR (U2.55)
AIIB.BUS-INTIN: XC3S500E-4PQ208 (U3#1.71), LEVELTRANSLATOR (U2.44)
AIIB.BUS-INTOUT: XC3S500E-4PQ208 (U3#1.68), LEVELTRANSLATOR (U2.43)
AIIB.BUS-IOSTROBE: XC3S500E-4PQ208 (U3#1.54), LEVELTRANSLATOR (U2.54)
AIIB.BUS-IRQ: XC3S500E-4PQ208 (U3#1.63), LEVELTRANSLATOR (U2.51)
AIIB.BUS-NMI: XC3S500E-4PQ208 (U3#1.65), LEVELTRANSLATOR (U2.45)
AIIB.BUS-PHASE0: XC3S500E-4PQ208 (U3#1.20), LEVELTRANSLATOR (U1.42)
AIIB.BUS-PHASE1: XC3S500E-4PQ208 (U3#1.26), LEVELTRANSLATOR (U2.74)
AIIB.BUS-Q3: XC3S500E-4PQ208 (U3#1.43), LEVELTRANSLATOR (U2.72)
AIIB.BUS-R/W: XC3S500E-4PQ208 (U3#1.50), LEVELTRANSLATOR (U2.61)
AIIB.BUS-RDY: XC3S500E-4PQ208 (U3#1.42), LEVELTRANSLATOR (U2.52)
AIIB.BUS-RESET: XC3S500E-4PQ208 (U3#1.60), LEVELTRANSLATOR (U2.53)
AIIB.BUS-SYNC: XC3S500E-4PQ208 (U3#1.57), LEVELTRANSLATOR (U2.56)
AIIB.BUS-USER1: XC3S500E-4PQ208 (U3#1.32), LEVELTRANSLATOR (U2.76)
AIIS.-BUS-DEV_SEL: APPLEIISLOT (J1.41), LEVELTRANSLATOR (U1.36)
AIIS.-BUS-IO_SEL: APPLEIISLOT (J1.1), LEVELTRANSLATOR (U1.6)
AIIS.BUS-3M58: APPLEIISLOT (J1.35), LEVELTRANSLATOR (U2.16)
AIIS.BUS-7M: APPLEIISLOT (J1.36), LEVELTRANSLATOR (U2.14)
AIIS.BUS-A0: APPLEIISLOT (J1.2), LEVELTRANSLATOR (U1.8)
AIIS.BUS-A1: APPLEIISLOT (J1.3), LEVELTRANSLATOR (U1.14)
AIIS.BUS-A2: APPLEIISLOT (J1.4), LEVELTRANSLATOR (U1.16)
AIIS.BUS-A3: APPLEIISLOT (J1.5), LEVELTRANSLATOR (U1.18)
AIIS.BUS-A4: APPLEIISLOT (J1.6), LEVELTRANSLATOR (U1.24)
AIIS.BUS-A5: APPLEIISLOT (J1.7), LEVELTRANSLATOR (U1.26)
AIIS.BUS-A6: APPLEIISLOT (J1.8), LEVELTRANSLATOR (U1.28)
AIIS.BUS-A7: APPLEIISLOT (J1.9), LEVELTRANSLATOR (U1.35)
AIIS.BUS-A8: APPLEIISLOT (J1.10), LEVELTRANSLATOR (U1.37)
AIIS.BUS-A9: APPLEIISLOT (J1.11), LEVELTRANSLATOR (U1.39)
AIIS.BUS-A10: APPLEIISLOT (J1.12), LEVELTRANSLATOR (U2.5)
AIIS.BUS-A11: APPLEIISLOT (J1.13), LEVELTRANSLATOR (U2.7)
AIIS.BUS-A12: APPLEIISLOT (J1.14), LEVELTRANSLATOR (U2.9)
AIIS.BUS-A13: APPLEIISLOT (J1.15), LEVELTRANSLATOR (U2.15)
AIIS.BUS-A14: APPLEIISLOT (J1.16), LEVELTRANSLATOR (U2.17)
AIIS.BUS-A15: APPLEIISLOT (J1.17), LEVELTRANSLATOR (U2.18)
AIIS.BUS-D0: APPLEIISLOT (J1.49), LEVELTRANSLATOR (U1.7)
AIIS.BUS-D1: APPLEIISLOT (J1.48), LEVELTRANSLATOR (U1.9)
AIIS.BUS-D2: APPLEIISLOT (J1.47), LEVELTRANSLATOR (U1.15)
AIIS.BUS-D3: APPLEIISLOT (J1.46), LEVELTRANSLATOR (U1.17)
AIIS.BUS-D4: APPLEIISLOT (J1.45), LEVELTRANSLATOR (U1.19)
AIIS.BUS-D5: APPLEIISLOT (J1.44), LEVELTRANSLATOR (U1.25)
AIIS.BUS-D6: APPLEIISLOT (J1.43), LEVELTRANSLATOR (U1.27)
AIIS.BUS-D7: APPLEIISLOT (J1.42), LEVELTRANSLATOR (U1.29)
AIIS.BUS-DMA: APPLEIISLOT (J1.22), LEVELTRANSLATOR (U2.34)
AIIS.BUS-DMAIN: APPLEIISLOT (J1.27), LEVELTRANSLATOR (U2.38)
AIIS.BUS-DMAOUT: APPLEIISLOT (J1.24), LEVELTRANSLATOR (U2.39)
AIIS.BUS-INH: APPLEIISLOT (J1.32), LEVELTRANSLATOR (U2.25)
AIIS.BUS-INTIN: APPLEIISLOT (J1.28), LEVELTRANSLATOR (U2.36)
AIIS.BUS-INTOUT: APPLEIISLOT (J1.23), LEVELTRANSLATOR (U2.37)
AIIS.BUS-IOSTROBE: APPLEIISLOT (J1.20), LEVELTRANSLATOR (U2.26)
AIIS.BUS-IRQ: APPLEIISLOT (J1.30), LEVELTRANSLATOR (U2.29)
AIIS.BUS-NMI: APPLEIISLOT (J1.29), LEVELTRANSLATOR (U2.35)
AIIS.BUS-PHASE0: APPLEIISLOT (J1.40), LEVELTRANSLATOR (U1.38)
AIIS.BUS-PHASE1: APPLEIISLOT (J1.38), LEVELTRANSLATOR (U2.6)
AIIS.BUS-Q3: APPLEIISLOT (J1.37), LEVELTRANSLATOR (U2.8)
AIIS.BUS-R/W: APPLEIISLOT (J1.18), LEVELTRANSLATOR (U2.19)
AIIS.BUS-RDY: APPLEIISLOT (J1.21), LEVELTRANSLATOR (U2.28)
AIIS.BUS-RESET: APPLEIISLOT (J1.31), LEVELTRANSLATOR (U2.27)
AIIS.BUS-SYNC: APPLEIISLOT (J1.19), LEVELTRANSLATOR (U2.24)
AIIS.BUS-USER1: APPLEIISLOT (J1.39), LEVELTRANSLATOR (U2.4)
BUS_ENABLE: XC3S500E-4PQ208 (U11.4), LEVELTRANSLATOR (8 pins)
CLK_EN: XC3S500E-4PQ208 (U3#1.128), PERIPHERAL (HDR1.49)
CLK_EXT0: XC3S500E-4PQ208 (U3#1.181), PERIPHERAL (HDR1.51)
CLK_EXT1: XC3S500E-4PQ208 (U3#1.132), PERIPHERAL (HDR1.45)
EXTSPI_CS_N0: XC3S500E-4PQ208 (R25.2 U3#1.74), PERIPHERAL (HDR1.59)
EXTSPI_CS_N1: XC3S500E-4PQ208 (R26.2 U3#1.75), PERIPHERAL (HDR1.63)
HOST_HARD_TCK_N: CON_10WBOXHDREDGEM (J2.3 R4.2), XC3S500E-4PQ208 (R32.1)
HOST_HARD_TDI_N: CON_10WBOXHDREDGEM (J2.1 R3.2), XC3S500E-4PQ208 (R30.1)
HOST_HARD_TDO_N: CON_10WBOXHDREDGEM (J2.2 R2.2), XC3S500E-4PQ208 (R31.1)
HOST_HARD_TMS_N: CON_10WBOXHDREDGEM (J2.4 R1.2), XC3S500E-4PQ208 (R33.1)
HOST_SOFT_TCK_N: CON_10WBOXHDREDGEM (R6.2), XC3S500E-4PQ208 (U3#1.184)
HOST_SOFT_TDI_N: CON_10WBOXHDREDGEM (R5.2), XC3S500E-4PQ208 (U3#1.159)
HOST_SOFT_TDO_N: CON_10WBOXHDREDGEM (J2.6 R10.2), XC3S500E-4PQ208 (U3#1.113)
HOST_SOFT_TMS_N: CON_10WBOXHDREDGEM (J2.8 R9.2), XC3S500E-4PQ208 (U3#1.154)
IDE.A0: XC3S500E-4PQ208 (U3#1.82), PERIPHERAL (HDR1.50), IDE (J4.35)
IDE.A1: XC3S500E-4PQ208 (U3#1.112), PERIPHERAL (HDR1.88), IDE (J4.33)
IDE.A2: XC3S500E-4PQ208 (U3#1.98), PERIPHERAL (HDR1.82), IDE (J4.36)
IDE.CS0: XC3S500E-4PQ208 (U3#1.2), PERIPHERAL (HDR1.90), IDE (J4.37)
IDE.CS1: XC3S500E-4PQ208 (U3#1.187), PERIPHERAL (HDR1.56), IDE (J4.38)
IDE.CSEL: XC3S500E-4PQ208 (U3#1.178), PERIPHERAL (HDR1.46), IDE (J4.28)
IDE.D0: XC3S500E-4PQ208 (U3#1.93), PERIPHERAL (HDR1.42), IDE (J4.17)
IDE.D1: XC3S500E-4PQ208 (U3#1.78), PERIPHERAL (HDR1.52), IDE (J4.15)
IDE.D2: XC3S500E-4PQ208 (U3#1.167), PERIPHERAL (HDR1.32), IDE (J4.13)
IDE.D3: XC3S500E-4PQ208 (U3#1.165), PERIPHERAL (HDR1.30), IDE (J4.11)
IDE.D4: XC3S500E-4PQ208 (U3#1.164), PERIPHERAL (HDR1.28), IDE (J4.9)
IDE.D5: XC3S500E-4PQ208 (U3#1.168), PERIPHERAL (HDR1.34), IDE (J4.7)
IDE.D6: XC3S500E-4PQ208 (U3#1.147), PERIPHERAL (HDR1.18), IDE (J4.5)
IDE.D7: XC3S500E-4PQ208 (U3#1.133), PERIPHERAL (HDR1.20), IDE (J4.3)
IDE.D8: XC3S500E-4PQ208 (U3#1.151), PERIPHERAL (HDR1.16), IDE (J4.4)
IDE.D9: XC3S500E-4PQ208 (U3#1.115), PERIPHERAL (HDR1.22), IDE (J4.6)
IDE.D10: XC3S500E-4PQ208 (U3#1.152), PERIPHERAL (HDR1.12), IDE (J4.8)
IDE.D11: XC3S500E-4PQ208 (U3#1.160), PERIPHERAL (HDR1.24), IDE (J4.10)
IDE.D12: XC3S500E-4PQ208 (U3#1.162), PERIPHERAL (HDR1.26), IDE (J4.12)
IDE.D13: XC3S500E-4PQ208 (U3#1.96), PERIPHERAL (HDR1.36), IDE (J4.14)
IDE.D14: XC3S500E-4PQ208 (U3#1.139), PERIPHERAL (HDR1.40), IDE (J4.16)
IDE.D15: XC3S500E-4PQ208 (U3#1.185), PERIPHERAL (HDR1.54), IDE (J4.18)
IDE.DASP: XC3S500E-4PQ208 (U3#1.189), PERIPHERAL (HDR1.58), IDE (J4.39)
IDE.DMACK: XC3S500E-4PQ208 (U3#1.172), PERIPHERAL (HDR1.38), IDE (J4.29)
IDE.DMARQ: XC3S500E-4PQ208 (U3#1.6), IDE (J4.21)
IDE.INTRQ: XC3S500E-4PQ208 (U3#1.175), IDE (J4.31)
IDE.IOCS16: XC3S500E-4PQ208 (U3#1.106), PERIPHERAL (HDR1.86), IDE (J4.32)
IDE.IORD: XC3S500E-4PQ208 (U3#1.180), PERIPHERAL (HDR1.48), IDE (J4.25)
IDE.IORDY: XC3S500E-4PQ208 (U3#1.194), IDE (J4.27)
IDE.IOWR: XC3S500E-4PQ208 (U3#1.177), PERIPHERAL (HDR1.44), IDE (J4.23)
IDE.PDIAG: XC3S500E-4PQ208 (U3#1.109), PERIPHERAL (HDR1.84), IDE (J4.34)
IDE.RESET: XC3S500E-4PQ208 (U3#1.153), PERIPHERAL (HDR1.14), IDE (J4.1)
ONE_WIRE_DB_PB: XC3S500E-4PQ208 (U3#1.203), PERIPHERAL (HDR1.61 HDR1.67)
PBIO29: XC3S500E-4PQ208 (U3#1.190), PERIPHERAL (HDR1.60)
PBIO30: XC3S500E-4PQ208 (U3#1.192), PERIPHERAL (HDR1.62)
PBIO31: XC3S500E-4PQ208 (U3#1.193), PERIPHERAL (HDR1.64)
PBIO32: XC3S500E-4PQ208 (U3#1.34), PERIPHERAL (HDR1.66)
PBIO33: XC3S500E-4PQ208 (U3#1.205), PERIPHERAL (HDR1.68)
PBIO34: XC3S500E-4PQ208 (U3#1.199), PERIPHERAL (HDR1.70)
PBIO35: XC3S500E-4PQ208 (U3#1.200), PERIPHERAL (HDR1.72)
PBIO36: XC3S500E-4PQ208 (U3#1.202), PERIPHERAL (HDR1.74)
PBIO37: XC3S500E-4PQ208 (U3#1.25), PERIPHERAL (HDR1.76)
PBIO38: XC3S500E-4PQ208 (U3#1.28), PERIPHERAL (HDR1.78)
PBIO39: XC3S500E-4PQ208 (U3#1.15), PERIPHERAL (HDR1.80)
RAM.NOE: XC3S500E-4PQ208 (U3#1.127), SRAM-128Kx8x2 (U9.28 U10.28)
RAM.NWE: XC3S500E-4PQ208 (U3#1.94), SRAM-128Kx8x2 (U9.12 U10.12)
ROM.BOOT_CS_N: XC3S500E-4PQ208 (U3#1.55), M25Pxx SPI_BOOT (U4.1)
ROM.DIN: XC3S500E-4PQ208 (U3#1.61), PERIPHERAL (HDR1.55), M25Pxx SPI_BOOT (U4.5), SDIO (J5.2 R40.1)
ROM.DOUT: XC3S500E-4PQ208 (U3#1.87), PERIPHERAL (HDR1.53), M25Pxx SPI_BOOT (U4.2), SDIO (J5.7 R42.1)
ROM.SCLK: XC3S500E-4PQ208 (U3#1.103), PERIPHERAL (HDR1.57), M25Pxx SPI_BOOT (U4.6), SDIO (J5.5 R41.1)
SD.DAT1: XC3S500E-4PQ208 (U3#1.56), PERIPHERAL (HDR1.96), SDIO (J5.8 R43.1)
SD.DAT2: XC3S500E-4PQ208 (U3#1.64), PERIPHERAL (HDR1.98), SDIO (J5.9 R38.1)
SD.DAT3: XC3S500E-4PQ208 (U3#1.62), PERIPHERAL (HDR1.100), SDIO (J5.1 R39.1)
SD.DETECT: XC3S500E-4PQ208 (U3#1.58), SDIO (J5.CD R36.1)
SD.PROTECT: XC3S500E-4PQ208 (U3#1.91), SDIO (J5.WP R37.1)
SRAM_A0: XC3S500E-4PQ208 (R24.1 U3#1.206), SRAM-128Kx8x2 (U9.1 U10.1)
SRAM_A1: XC3S500E-4PQ208 (U3#1.126), SRAM-128Kx8x2 (U9.2 U10.2)
SRAM_A2: XC3S500E-4PQ208 (U3#1.123), SRAM-128Kx8x2 (U9.3 U10.3)
SRAM_A3: XC3S500E-4PQ208 (U3#1.122), SRAM-128Kx8x2 (U9.4 U10.4)
SRAM_A4: XC3S500E-4PQ208 (U3#1.179), SRAM-128Kx8x2 (U9.13 U10.13)
SRAM_A5: XC3S500E-4PQ208 (R27.2 U3#1.84), SRAM-128Kx8x2 (U9.14 U10.14)
SRAM_A6: XC3S500E-4PQ208 (R28.2 U3#1.86), SRAM-128Kx8x2 (U9.15 U10.15)
SRAM_A7: XC3S500E-4PQ208 (U3#1.197), SRAM-128Kx8x2 (U9.16 U10.16)
SRAM_A8: XC3S500E-4PQ208 (U3#1.196), SRAM-128Kx8x2 (U9.17 U10.17)
SRAM_A9: XC3S500E-4PQ208 (U3#1.186), SRAM-128Kx8x2 (U9.18 U10.18)
SRAM_A10: XC3S500E-4PQ208 (U3#1.100), SRAM-128Kx8x2 (U9.19 U10.19)
SRAM_A11: XC3S500E-4PQ208 (U3#1.102), SRAM-128Kx8x2 (U9.20 U10.20)
SRAM_A12: XC3S500E-4PQ208 (U3#1.99), SRAM-128Kx8x2 (U9.21 U10.21)
SRAM_A13: XC3S500E-4PQ208 (U3#1.134), SRAM-128Kx8x2 (U9.29 U10.29)
SRAM_A14: XC3S500E-4PQ208 (U3#1.135), SRAM-128Kx8x2 (U9.30 U10.30)
SRAM_A15: XC3S500E-4PQ208 (U3#1.138), SRAM-128Kx8x2 (U9.31 U10.31)
SRAM_A16: XC3S500E-4PQ208 (U3#1.137), SRAM-128Kx8x2 (U9.32 U10.32)
SRAM_D0: XC3S500E-4PQ208 (U3#1.116), SRAM-128Kx8x2 (U9.6 U10.6)
SRAM_D1: XC3S500E-4PQ208 (U3#1.163), SRAM-128Kx8x2 (U9.7 U10.7)
SRAM_D2: XC3S500E-4PQ208 (U3#1.171), SRAM-128Kx8x2 (U9.10 U10.10)
SRAM_D3: XC3S500E-4PQ208 (U3#1.90), SRAM-128Kx8x2 (U9.11 U10.11)
SRAM_D4: XC3S500E-4PQ208 (U3#1.76), SRAM-128Kx8x2 (U9.22 U10.22)
SRAM_D5: XC3S500E-4PQ208 (U3#1.120), SRAM-128Kx8x2 (U9.23 U10.23)
SRAM_D6: XC3S500E-4PQ208 (U3#1.97), SRAM-128Kx8x2 (U9.26 U10.26)
SRAM_D7: XC3S500E-4PQ208 (U3#1.129), SRAM-128Kx8x2 (U9.27 U10.27)
SRAM_NCS0: XC3S500E-4PQ208 (U3#1.161), SRAM-128Kx8x2 (U9.5)
SRAM_NCS1: XC3S500E-4PQ208 (U3#1.119), SRAM-128Kx8x2 (U10.5)
SYS_JTAG.VREF: CON_10WBOXHDREDGEM (J2.10), XC3S500E-4PQ208 (R34.2)
SYSCLK.SYSCLK: XC3S500E-4PQ208 (U3#1.183), SYSCLK (R50.2)
VGA.BLUE0: XC3S500E-4PQ208 (U3#1.145), PERIPHERAL (HDR1.6), SVGA (R48.2)
VGA.BLUE1: XC3S500E-4PQ208 (U3#1.146), PERIPHERAL (HDR1.8), SVGA (R49.2)
VGA.GREEN0: XC3S500E-4PQ208 (U3#1.140), PERIPHERAL (HDR1.2), SVGA (R46.2)
VGA.GREEN1: XC3S500E-4PQ208 (U3#1.144), PERIPHERAL (HDR1.4), SVGA (R47.2)
VGA.HSYNC: XC3S500E-4PQ208 (U3#1.89), PERIPHERAL (HDR1.92), SVGA (J6.3 J7.4)
VGA.RED0: XC3S500E-4PQ208 (U3#1.83), PERIPHERAL (HDR1.47), SVGA (R44.2)
VGA.RED1: XC3S500E-4PQ208 (U3#1.150), PERIPHERAL (HDR1.10), SVGA (R45.2)
VGA.SCL: XC3S500E-4PQ208 (U3#1.108), PERIPHERAL (HDR1.25), SVGA (J6.11 J7.6)
VGA.SDA: XC3S500E-4PQ208 (U3#1.107), PERIPHERAL (HDR1.27), SVGA (J6.10 J7.5)
VGA.VSYNC: XC3S500E-4PQ208 (U3#1.77), PERIPHERAL (HDR1.94), SVGA (J6.2 J7.9)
